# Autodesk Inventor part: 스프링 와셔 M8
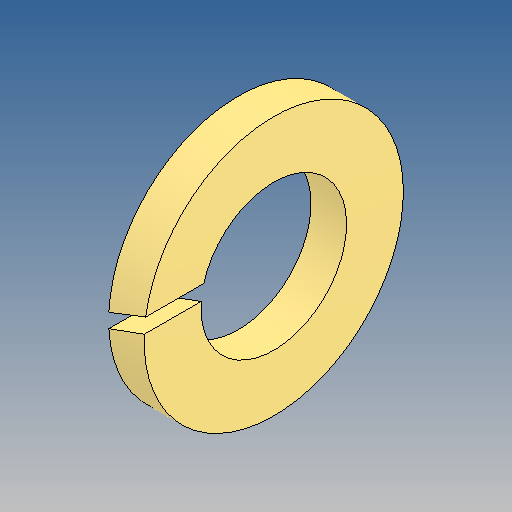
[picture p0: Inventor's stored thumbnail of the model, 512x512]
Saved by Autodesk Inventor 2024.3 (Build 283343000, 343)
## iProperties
Created: 2025-06
Part Number: 스프링 와셔 M8
Material: 강철, 연강
Description: 스프링 잠금 와셔
Document SubType Name: Modeling
Designer: user
Density: 7.85 g/cm^3
Appearance: 기본값
Author: jhkim
Sending System: Autodesk Inventor 2026
Preprocessor: ST-DEVELOPER v20.1
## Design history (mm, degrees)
node "스프링 와셔 M81"
node "솔리드1"
body "Solid1"
